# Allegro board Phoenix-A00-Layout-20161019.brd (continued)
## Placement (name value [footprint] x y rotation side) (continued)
RB11  0_5%  [R0402]  13.5 157.1 180 top
RB12  10K_5%  [R0402]  13.5 156.08 0 top
RB13  10K_5%  [R0402]  13.5 151 0 top
RB16  100_1%  [R0402]  10.7 118.36 180 top
RB17  0_5%  [R0402]  13.37 142.37 180 top
RB18  0_5%  [R0402]  15.4 142.37 0 top
RB19  0_5%  [R0402]  13.37 143.38 180 top
RB20  0_5%  [R0402]  15.4 143.38 0 top
RB21  0_5%  [R0402]  13.37 146.43 180 top
RB22  0_5%  [R0402]  15.4 146.43 0 top
RB23  0_5%  [R0402]  13.37 145.41 180 top
RB24  0_5%  [R0402]  15.4 145.41 0 top
RB25  0_5%  [R0402]  13.37 144.4 180 top
RB26  0_5%  [R0402]  15.4 144.4 0 top
RB27  0_5%  [R0402]  13.5 152.02 180 top
RB28  0_5%  [R0402]  15.4 147.45 0 top
RC1  1nF_X7R_16V  [C0402]  67.85 180.72 0 top
RD1  10K_5%  [R0402]  144.81 74.04 90 top
RD2  0_5%  [R0402]  149.77 75.18 90 top
RD3  470_1%  [R0402]  150.78 75.18 90 top
RD4  SHORT-PAD-4  [R0402_S4MIL_MVB]  151.8 75.18 270 top
RD5  240_1%  [R0402]  142.27 75.25 90 top
RD6  1K_1%  [R0402]  219.08 84.51 90 top
RD7  1K_1%  [R0402]  220.1 84.51 270 top
RD8  SHORT-PAD-10  [R0402_S10MIL_MVB]  221.09 84.53 270 top
RD9  2_1%  [R0402]  226.78 84.53 270 top
RD10  24.9_1%  [R0402]  228.91 84.53 270 top
REAR_AUDIO  HDA_X1_GF_Lime  [AUDIO_5_472X563_OBLONG]  233.67 256.72 0 top
RF1  3.3K_5%  [R0402]  198.79 223.52 0 top
RF2  15K_1%  [R0402]  201.71 221.87 270 top
RF3  6.2K_1%  [R0402]  203.23 222.38 0 top
RF4  0_5%  [R0805]  214.41 229.87 180 top
RF5  2.2K_5%  [R0402]  220.12 231.39 0 top
RF6  100_5%  [R0402]  237.78 136.52 0 top
RF7  0_5%  [R0402]  233.71 135.38 270 top
RF8  220_5%  [R0402]  236.51 118.62 90 top
RF9  1K_5%  [R0402]  235.49 118.62 270 top
RF10  0_5%  [R0805]  231.3 130.56 90 top
RF11  100K_1%  [R0402]  221.65 230.12 270 top
RF12  3K_1%  [R0402]  223.93 230.25 90 top
RF13  3.3K_5%  [R0402]  218.73 226.44 270 top
RF14  7.15K_1%  [R0603]  219.74 230.25 180 top
RF15  10K_1%  [R0402]  216.82 225.04 270 top
RF16  33_5%  [R0402]  27.08 109.09 180 top
RF17  33_5%  [R0402]  27.47 110.74 90 top
RF18  33_5%  [R0402]  27.47 112.78 270 top
RF21  33_5%  [R0402]  27.47 114.81 90 top
RF23  33_5%  [R0402]  28.48 103.38 270 top
RF24  33_5%  [R0402]  38.39 110.11 90 top
RF25  4.7K_5%  [R0402]  39.15 93.09 180 top
RF26  10K_5%  [R0402]  39.15 94.11 0 top
RF27  10K_5%  [R0402]  28.99 99.19 270 top
RF28  33_5%  [R0402]  30.01 94.62 0 top
RF29  10K_5%  [R0402]  33.56 89.92 90 top
RF30  10K_5%  [R0402]  39.15 95.12 0 top
RF32  0_5%  [R0402]  33.56 100.97 270 top
RF33  8.2K_5%  [R0402]  30.51 97.66 180 top
RF34  8.2K_5%  [R0402]  33.56 98.93 270 top
RF37  0_5%  [R0402]  30.01 95.63 0 top
RF39  0_5%  [R0402]  30.01 93.6 0 top
RF41  0_5%  [R0402]  32.29 89.92 90 top
RF43  0_5%  [R0402]  27.97 95.25 270 top
RF45  0_5%  [R0402]  30.01 96.65 0 top
RF53  0_5%  [R0402]  35.72 98.93 270 top
RF54  0_5%  [R0603]  38.39 97.79 270 top
RF55  0_5%  [R0603]  38.39 100.58 90 top
RF56  10K_5%  [R0402]  27.97 97.28 270 top
RF59  SHORT-PAD-15  [R0603_S15MIL_MVB]  39.15 105.41 0 top
RF60  33_5%  [R0402]  40.29 107.06 90 top
RF61  33_5%  [R0402]  38.77 107.44 180 top
RF62  0_5%  [R0603]  29.62 91.44 180 top
RF63  10K_5%  [R0402]  39.15 92.07 180 top
RF64  10K_5%  [R0402]  34.83 89.92 90 top
RF76  0_5%  [R0402]  27.47 125.98 0 top
RF77  2.2K_5%  [R0402]  20.99 149.73 0 top
RF176  30_5%  [R0402]  25.69 128.65 180 top
RF177  0_5%  [R0402]  25.31 125.98 0 top
RF178  22_5%  [R0402]  20.99 145.16 0 top
RF179  22_5%  [R0402]  23.02 149.73 0 top
RF180  0_5%  [R0805]  215.17 233.04 90 top
RG3  0_5%  [R0402]  149.53 220.22 270 top
RG4  0_5%  [R0402]  150.54 220.22 270 top
RG5  4.7K_5%  [R0402]  148.51 220.22 90 top
RG6  4.7K_5%  [R0402]  151.56 220.22 90 top
RG7  100K_5%  [R0402]  143.05 225.81 180 top
RG8  100K_5%  [R0402]  143.05 228.85 180 top
RG9  4.7K_5%  [R0402]  149.78 229.74 180 top
RG10  4.7K_5%  [R0402]  149.27 231.27 90 top
RG11  4.7K_5%  [R0402]  147.1 232.66 270 top
RG12  4.7K_5%  [R0402]  147.1 230.25 90 top
RG13  4.7K_5%  [R0402]  148.12 232.66 270 top
RG14  4.7K_5%  [R0402]  148.12 230.25 90 top
RG15  75_1%  [R0402]  155.99 224.28 90 top
RG16  75_1%  [R0402]  155.99 226.19 90 top
RG17  75_1%  [R0402]  155.99 228.09 90 top
RG18  36_1%  [R0402]  173.66 235.08 0 top
RG19  36_1%  [R0402]  171.12 235.08 0 top
RG20  2.2K_5%  [R0402]  156.75 232.66 0 top
RG21  2.2K_5%  [R0402]  156.75 231.65 0 top
RG22  10K_5%  [R0402]  190.84 232.54 90 top
RG23  0_5%  [R0402]  191.86 232.54 270 top
RG24  0_5%  [R0402]  161.72 233.17 90 top
RG25  0_5%  [R0402]  170.48 227.33 180 top
RG27  12K_1%  [R0402]  145.72 225.93 180 top
RG28  0_5%  [R0402]  144.18 215.77 0 top
RG29  100K_5%  [R0402]  142.65 218.57 90 top
RG30  0_5%  [R0402]  146.21 215.77 180 top
RG31  4.7K_5%  [R0402]  153.83 230.12 90 top
RG32  4.7K_5%  [R0402]  154.34 228.6 180 top
RH1  2.2K_5%  [R0402]  114.97 199.01 90 top
RH2  1K_5%  [R0402]  115.73 195.96 270 top
RH3  1K_5%  [R0402]  137.19 176.4 270 top
RH4  8.2K_5%  [R0402]  63.79 109.47 90 top
RH5  8.2K_5%  [R0402]  52.1 90.93 90 top
RH6  8.2K_5%  [R0402]  38.26 123.06 270 top
RH7  10K_5%  [R0402]  62.39 109.47 270 top
RH8  8.2K_5%  [R0402]  60.99 106.93 270 top
RH9  10K_5%  [R0402]  60.99 109.47 90 top
RH10  10K_5%  [R0402]  65.44 107.19 270 top
RI1  10_1%  [R0402]  217.84 242.19 180 top
RI2  10_1%  [R0402]  216.82 239.01 90 top
RI3  10_1%  [R0402]  225.2 239.01 90 top
RI4  10_1%  [R0402]  227.57 239.27 0 top
RIO2  1K_5%  [R0402]  213.84 20.62 270 top
RIO3  100_5%  [R0402]  214.86 20.62 270 top
RIO6  10K_5%  [R0402]  41.82 149.61 0 top
RIO8  499_1%  [R0603]  217.52 19.35 90 top
RIO9  390_1%  [R0603]  217.52 16.56 270 top
RIO10  1K_5%  [R0402]  201.96 12.4 180 top
RIO11  1K_5%  [R0402]  195.87 12.45 180 top
RK4  2.7K_5%  [R0402]  47.48 169.49 90 top
RK5  2.7K_5%  [R0402]  46.46 169.49 270 top
RK6  49.9_1%  [R0402]  57.56 186.44 90 top
RK7  232_1%  [R0603]  50.2 202.06 0 top
RK8  14.3K_1%  [R0402]  50.2 203.2 0 top
RK9  0_5%  [R0402]  51.34 207.77 270 top
RK10  0_5%  [R0402]  35.09 192.91 180 top
RK11  10K_5%  [R0402]  56.55 184.02 90 top
RK13  100_1%  [R0603]  34.58 206.63 0 top
RK14  0_5%  [R0402]  60.74 205.74 90 top
RK18  22_5%  [R0402]  63.03 186.44 270 top
RK19  0_5%  [R0402]  35.09 191.9 180 top
RK22  10K_5%  [R0402]  57.56 184.02 90 top
RK24  10K_5%  [R0402]  62.77 208.53 90 top
RK25  10K_5%  [R0402]  61.76 205.74 270 top
RK27  10K_5%  [R0402]  55.02 181.99 0 top
RK28  10K_5%  [R0402]  49.82 206.76 0 top
RK30  0_5%  [R0402]  26.58 219.71 0 top
RK31  10K_5%  [R0402]  53.88 187.58 90 top
RK32  10K_5%  [R0402]  61.76 208.53 90 top
RK33  10K_5%  [R0402]  58.58 186.44 90 top
RK34  1K_5%  [R0402]  55.41 205.74 270 top
RK35  1K_5%  [R0402]  52.87 205.28 0 top
RK36  10K_5%  [R0402]  55.41 208.34 90 top
RK37  10K_5%  [R0402]  63.03 184.02 270 top
RK38  10K_5%  [R0402]  56.55 186.44 270 top
RK39  10K_5%  [R0402]  54.39 205.74 270 top
RK40  0_5%  [R0402]  50.2 208.28 90 top
RK41  10K_5%  [R0402]  55.41 186.44 90 top
RK42  1K_5%  [R0402]  69.25 191.77 0 top
RK43  51K_1%  [R0402]  67.85 181.74 0 top
RK44  1K_1%  [R0402]  65.82 181.74 180 top
RK45  56K_1%  [R0402]  69.88 181.74 0 top
RK46  10K_5%  [R0402]  58.58 184.02 270 top
RK47  10K_5%  [R0402]  59.6 186.44 270 top
RK48  10K_5%  [R0402]  59.6 184.02 270 top
RK49  10K_5%  [R0402]  61.63 186.44 270 top
RK50  2.7K_5%  [R0402]  26.7 164.59 180 top
RK51  0_5%  [R0402]  26.82 193.32 0 top
RK52  0_5%  [R0402]  26.82 192.23 0 top
RK53  0_5%  [R0402]  26.61 218.77 0 top
RK54  2.7K_5%  [R0402]  26.7 165.61 0 top
RK55  100_1%  [R0603]  29.5 202.18 0 top
RK56  22_5%  [R0402]  60.61 186.44 270 top
RL1  10K_5%  [R0402]  102.4 226.57 0 top
RL3  4.7K_5%  [R0402]  106.97 221.23 90 top
RL12  0_5%  [R0402]  115.73 226.82 0 top
RL28  330_1%  [R0402]  115.73 223.77 0 top
RL29  330_1%  [R0402]  115.73 224.79 0 top
RL30  330_1%  [R0402]  115.73 225.81 0 top
RL32  SHORT-PAD-10  [R0402_S10MIL_MVB]  102.4 227.58 0 top
RL33  2.49K_1%  [R0402]  117.76 228.85 180 top
RL34  1K_5%  [R0402]  104.94 221.23 90 top
RL35  15K_5%  [R0402]  105.95 221.23 270 top
RL36  0_5%  [R0402]  115.48 221.36 270 top
RL37  10K_5%  [R0402]  54.14 250.19 0 top
RL38  SHORT-PAD-10  [R0402_S10MIL_MVB]  53.25 251.71 90 top
RL39  8.2K_5%  [R0402]  53.25 253.75 270 top
RL40  8.2K_5%  [R0402]  64.68 253.75 270 top
RL41  10K_5%  [R0402]  59.47 250.19 0 top
RL42  39K_5%  [R0402]  64.68 251.71 270 top
RL43  0_5%  [R0402]  66.96 253.75 90 top
RL44  0_5%  [R0402]  119.54 231.39 90 top
RM1  0_5%  [R0402]  100.74 144.53 90 top
RM2  1K_5%  [R0402]  99.73 144.53 90 top
RM3  10K_5%  [R0402]  102.78 144.91 180 top
RM4  0_5%  [R0402]  99.47 131.95 0 top
RM5  SHORT-PAD-4  [R0402_S4MIL]  101.51 133.22 270 top
RM6  10K_5%  [R0402]  112.43 132.21 180 top
RM7  10K_5%  [R0402]  110.14 132.46 0 top
RM8  1K_5%  [R0402]  113.19 133.73 270 top
RM15  0_5%  [R0402]  101.13 121.28 90 top
RM16  0_5%  [R0402]  100.11 121.28 90 top
RN5  4.7K_5%  [8P4R0603V]  153.96 238.46 0 top
RNF2  4.7K_5%  [8P4R0402V]  233.46 132.59 0 top
RNK1  8.2K_5%  [8P4R0603V]  58.33 206.25 0 top
RNK4  4.7K_5%  [8P4R0402V]  47.66 244.98 90 top
RNK5  8.2K_5%  [8P4R0603V]  69.07 194.18 270 top
RNK6  8.2K_5%  [8P4R0603V]  69.12 202.69 270 top
RNK7  4.7K_5%  [8P4R0402V]  26.96 241.17 90 top
RNO1  10K_5%  [8P4R0402V]  208.95 54.86 180 top
RNO2  8.2K_5%  [8P4R0603V]  205.11 16.41 270 top
RNO5  1K_5%  [8P4R0402V]  222.86 17.95 90 top
RNX4  4.7K_5%  [8P4R0402V]  87.41 232.03 0 top
RO2  SHORT-PAD-4  [R0402_S4MIL_MVB]  208.19 35.56 90 top
RO3  0_5%  [R0402]  213.77 55.5 180 top
RO4  SHORT-PAD-4  [R0402_S4MIL_MVB]  218.85 33.66 90 top
RO5  2M_5%  [R0402]  215.93 31.12 180 top
RO7  0_5%  [R0402]  213.77 54.48 180 top
RO8  SHORT-PAD-4  [R0402_S4MIL_MVB]  219.87 33.66 90 top
RO9  4.7K_5%  [R0402]  231.05 47.62 0 top
RO10  43_1%  [R0402]  223.3 31.24 90 top
RO11  160_5%  [R0402]  210.73 54.99 90 top
RO12  1K_5%  [R0402]  225.33 31.24 90 top
RO13  33_5%  [R0402]  212.5 34.54 270 top
RO16  SHORT-PAD-4  [R0402_S4MIL_MVB]  206.79 52.07 0 top
RO18  SHORT-PAD-4  [R0402_S4MIL_MVB]  206.79 53.09 0 top
RO19  SHORT-PAD-4  [R0402_S4MIL_MVB]  223.43 54.99 270 top
RO21  8.2K_5%  [R0402]  226.98 44.45 0 top
RO22  SHORT-PAD-4  [R0402_S4MIL_MVB]  222.41 54.99 90 top
RO23  10K_5%  [R0402]  211.23 56.51 180 top
RO24  0_5%  [R0402]  204.63 38.1 0 top
RO25  2.7K_5%  [R0402]  217.33 54.99 270 top
RO26  2.7K_5%  [R0402]  216.31 54.99 270 top
RO27  10K_5%  [R0402]  211.74 54.99 270 top
RO28  1K_5%  [R0402]  206.66 37.08 0 top
RO31  47K_5%  [R0402]  220.38 57.53 270 top
RO32  8.2K_5%  [R0402]  231.05 48.64 180 top
RO33  220_5%  [R0402]  226.98 48.9 180 top
RO35  15K_5%  [R0402]  220.38 54.99 270 top
RO36  330K_5%  [R0402]  226.73 33.66 270 top
RO39  8.2K_5%  [R0402]  206.15 35.56 90 top
RO43  30K_1%  [R0402]  204.5 50.04 180 top
RO44  9.1K_1%  [R0402]  200.19 47.88 90 top
RO45  7.15K_1%  [R0603]  199.04 48.26 270 top
RO46  10K_1%  [R0402]  7.15 69.6 0 top
RO48  33K_1%  [R0402]  200.31 50.55 270 top
RO50  20K_1%  [R0402]  7.15 70.61 0 top
RO51  9.1K_1%  [R0402]  204.5 51.05 180 top
RO52  10K_1%  [R0402]  12.86 69.72 90 top
RO53  1.65K_1%  [R0402]  7.4 72.14 90 top
RO54  6.8K_1%  [R0402]  204 52.58 90 top
RO55  30K_1%  [R0402]  214.92 61.09 180 top
RO56  8.2K_1%  [R0402]  213.39 61.59 270 top
RO57  698_1%  [R0402]  212.38 61.59 90 top
RO80  2.7K_5%  [R0402]  218.47 59.06 180 top
RO81  SHORT-PAD-4  [R0402_S4MIL_MVB]  221.39 54.99 270 top
RO89  33_5%  [R0402]  222.28 33.66 90 top
RO99  0_5%  [R0402]  215.3 54.99 270 top
RO100  10_1%  [R0402]  213.77 56.51 180 top
RO102  10_1%  [R0402]  217.33 61.09 180 top
RO117  8.2K_5%  [R0402]  231.05 49.66 180 top
RO118  10_1%  [R0402]  207.42 57.4 0 top
RO163  2.7K_5%  [R0402]  218.47 59.94 180 top
RO166  SHORT-PAD-4  [R0402_S4MIL_MVB]  229.4 45.47 180 top
RO167  22K_5%  [R0402]  221.39 57.53 90 top
RO168  30K_1%  [R0402]  204.63 44.83 90 top
RO169  8.2K_5%  [R0402]  207.17 35.56 270 top
RO170  2K_1%  [R0402]  200.31 52.58 270 top
RO171  9.1K_1%  [R0402]  200.06 44.07 90 top
RO172  10K_1%  [R0402]  201.58 43.56 180 top
RO174  0_5%  [R0402]  206.66 38.1 180 top
RO176  1K_5%  [R0402]  226.98 45.47 0 top
RO179  8.2K_5%  [R0402]  226.73 31.24 90 top
RO187  8.2K_5%  [R0402]  231.05 46.61 180 top
RO188  10_1%  [R0402]  221.9 28.96 270 top
RO189  16K_1%  [R0402]  14 69.72 270 top
RP5  51_5%  [R0402]  45.5 139.45 90 top
RP8  51_5%  [R0402]  48.17 144.02 90 top
RP25  10K_5%  [R0402]  54.26 109.22 270 top
RP26  SHORT-PAD-4  [R0402_S4MIL_MVB]  48.29 104.27 270 top
RP34  0_5%  [R0402]  62.14 139.95 0 top
RP35  0_5%  [R0402]  62.14 139.06 0 top
RP36  SHORT-PAD-15  [R0603_S15MIL_MVB]  58.33 109.6 270 top
RP37  SHORT-PAD-15  [R0603_S15MIL_MVB]  43.21 136.02 270 top
RP38  SHORT-PAD-15  [R0603_S15MIL_MVB]  46.13 109.35 90 top
RP40  10K_5%  [R0402]  54.26 106.81 90 top
RP41  10K_5%  [R0402]  60.99 102.11 90 top
RP42  SHORT-PAD-15  [R0603_S15MIL_MVB]  42.32 129.41 0 top
RS13  0_5%  [R0402]  56.93 90.81 90 top
RS14  0_5%  [R0402]  50.83 90.93 90 top
RS16  0_5%  [R0402]  116.75 195.96 270 top
RS17  0_5%  [R0402]  49.56 90.93 90 top
RS18  0_5%  [R0402]  43.57 102.59 0 top
RS21  0_5%  [R0402]  47.12 90.88 90 top
RS22  1K_5%  [R0402]  43.57 101.56 0 top
RS89  1K_5%  [R0402]  218.85 31.24 90 top
RS90  1K_5%  [R0402]  219.87 31.24 90 top
RS123  1K_1%  [R0402]  63.79 104.78 90 top
RS124  10K_5%  [R0402]  58.96 106.81 270 top
RS127  10K_5%  [R0402]  58.96 104.52 90 top
RS129  10K_5%  [R0402]  63.79 102.74 90 top
RS159  8.2K_5%  [R0402]  152.26 41.81 0 top
RS161  1K_5%  [R0402]  149.33 46.2 180 top
RS162  10K_5%  [R0402]  150.22 40.87 180 top
RS166  4.7K_5%  [R0402]  135.54 45.21 90 top
RS169  0_5%  [R0402]  116.24 197.43 180 top
RS222  1K_5%  [R0402]  150.22 41.81 180 top
RS223  0_5%  [R0402]  47.53 141.99 90 top
RS224  0_5%  [R0402]  45.25 141.99 90 top
RS225  0_5%  [R0402]  46.52 139.45 90 top
RS226  0_5%  [R0402]  47.53 139.45 90 top
RS227  1K_5%  [R0402]  46.52 141.99 270 top
RS232  1K_5%  [R0402]  45.05 101.79 270 top
RS233  10K_5%  [R0402]  46.13 106.43 270 top
RS234  1K_1%  [R0402]  46.13 104.14 270 top
RS235  10K_5%  [R0402]  40.55 114.05 0 top
RS236  1K_1%  [R0402]  42.83 114.05 0 top
RST_SWH  Tact Switch_Brown  [SW_2_236X150]  9.56 113.54 270 top
RTK_LAN  RTL8111HSD-CG_A  [QFN_32_16_157X157_TH106_H35]  110.65 227.2 270 top
RTK_VGA  RTD2168-CGT_E  [QFN32C1]  151.43 224.92 90 top
RU3  0_5%  [R0603]  97.52 245.87 180 top
RU4  0_5%  [R0603]  97.52 247.14 180 top
RU5  0_5%  [R0603]  97.52 243.33 180 top
RU10  0_5%  [R0603]  134.48 235.71 90 top
RU12  0_5%  [R0603]  133.21 235.71 90 top
RU13  0_5%  [R0603]  130.67 235.71 90 top
RU15  0_5%  [R0603]  131.94 235.71 90 top
RU26  10K_1%  [R0402]  131.22 228.98 180 top
RU29  15K_1%  [R0402]  130.72 227.46 270 top
RU46  8.2K_5%  [R0402]  63.79 107.19 270 top
RU47  15K_1%  [R0402]  137.32 21.42 270 top
RU54  0_5%  [R0603]  151.68 24.36 270 top
RU55  0_5%  [R0603]  150.41 24.36 270 top
RU58  0_5%  [R0603]  147.87 24.36 270 top
RU59  0_5%  [R0603]  149.14 24.36 270 top
RU62  0_5%  [R0603]  42.83 75.18 0 top
RU63  0_5%  [R0603]  42.83 73.91 0 top
RU66  0_5%  [R0603]  42.83 77.85 0 top
RU67  0_5%  [R0603]  42.83 76.58 0 top
RU68  15K_1%  [R0402]  55.41 75.18 180 top
RU69  10K_1%  [R0402]  55.66 73.66 270 top
RU120  0_5%  [R0603]  97.52 244.6 180 top
RU134  10K_1%  [R0402]  154.29 26.02 90 top
RU135  15K_1%  [R0402]  153.27 26.02 270 top
RU147  10K_1%  [R0402]  136.3 21.42 90 top
RU174  8.2K_5%  [R0402]  48.55 109.22 90 top
RV45  470_1%  [R0402]  208.57 244.98 90 top
RV46  470_1%  [R0402]  206.75 245.01 90 top
RV47  470_1%  [R0402]  205.48 245.01 90 top
RV48  470_1%  [R0402]  209.84 244.98 90 top
RV49  470_1%  [R0402]  211.58 245.01 270 top
RV72  470_1%  [R0402]  212.85 245.01 270 top
RV73  470_1%  [R0402]  214.63 245.01 270 top
RV74  470_1%  [R0402]  215.9 245.01 270 top
RV75  SHORT-PAD-4  [R0402_S4MIL_MVB]  219.49 235.97 90 top
RV76  SHORT-PAD-4  [R0402_S4MIL_MVB]  220.47 242.09 90 top
RV77  1M_5%  [R0402]  229.6 239.27 180 top
RV79  20K_5%  [R0402]  224.19 241.3 270 top
RV80  100K_5%  [R0402]  226.55 241.3 270 top
RV84  SHORT-PAD-4  [R0402_S4MIL_MVB]  222.54 235.97 90 top
RV85  SHORT-PAD-4  [R0402_S4MIL_MVB]  221.48 242.09 90 top
RV86  2.2K_1%  [R0402]  220.51 235.97 90 top
RV87  2.2K_1%  [R0402]  221.52 235.97 90 top
RV88  2.2K_1%  [R0402]  224.4 243.49 180 top
RV89  2.2K_1%  [R0402]  226.44 243.49 0 top
RX6  0_5%  [R0402]  86.52 227.46 90 top
RX7  0_5%  [R0402]  87.54 227.46 90 top
RX16  4.7K_5%  [R0402]  66.58 233.17 180 top
RX17  4.7K_5%  [R0402]  66.58 232.16 180 top
RX18  4.7K_5%  [R0402]  66.58 231.14 180 top
RX19  0_5%  [R0402]  66.58 235.2 180 top
RX20  0_5%  [R0402]  66.58 234.19 180 top
RX21  150_1%  [R0402]  126.15 193.04 0 top
RX165  10K_5%  [R0402]  64.8 215.52 180 top
RX175  0_5%  [R0402]  75.6 234.7 0 top
RX176  0_5%  [R0402]  75.6 233.68 0 top
RX181  33_5%  [R0402]  49.56 250.7 180 top
RX182  SHORT-PAD-4  [R0402_S4MIL_MVB]  46.39 251.71 180 top
RX185  10K_1%  [R0402]  33.05 119.25 0 top
RX199  SHORT-PAD-4  [R0402_S4MIL_MVB]  41.31 142.11 90 top
RX200  33_5%  [R0402]  42.32 144.65 90 top
RX201  0_5%  [R0402]  42.32 142.11 90 top
RX202  0_5%  [R0402]  41.31 144.65 90 top
SATA0  SATA_S_15u_Blue  [SATA7_LE18]  121.67 70.41 0 top
SATA1  SATA_S_15u_White  [SATA7_LE18]  139.9 70.41 0 top
SATA2  SATA_S_15u_Black  [SATA7_LE18]  139.9 59.81 0 top
SATA_PWR  PWR_2X3_K6_4.2_Black  [PWR_2X3_165_547X378_O6]  104.36 41.07 180 top
SIO_5553  SCH5553-NU_C  [VTQFP_128_16_630]  216.69 44.69 90 top
SLOT1  PCIE-X16_164P_15u_Blue  [PCIE164_X16_RM_POUDRE]  83.15 238.78 90 top
SLOT2  PCIEX1_36P_15u_Black  [PCIE36_X1]  61.43 227.13 270 top
SLOT3  PCI_120P_15u  [PCI120]  41.11 244.85 0 top
SLOT4  PCI_120P_15u  [PCI120]  20.79 244.85 0 top
SPI1  MX25L12873FM2I-10G  [SOP8JG]  32.93 108.84 90 top
SPI_1  SPI_8P_100u_Black  [SOP8JA_SOCKET2]  32.93 108.84 270 top
SSUSB_R  USB3X2_15u_Blue  [USB3X4_18_79]  134.41 247.1 180 top
SW_FVS  TEST POINT  [FVS_DELL]  211.87 24.72 0 top
THRM_1  ST2N3904-TDF4001-HAF  [TO92_EBC_H310]  7.59 79.63 270 top
THRM_2  ST2N3904-TDF4001-HAF  [TO92_EBC_H310]  68.11 148.97 270 top
TPS1  TP_SMD  [TPC30B]  43.21 121.54 0 top
TPS5  TP_SMD  [TPC30B]  211.49 47.37 0 top
TPS8  TP_SMD  [TPC30B]  170.47 141.1 0 top
TPS9  TP_SMD  [TPC30B]  169.61 139.34 0 top
TPS13  TP_SMD  [TPC22B30D12]  146.97 129.34 0 top
TPS14  TP_SMD  [TPC22B30D12]  146.31 130.91 0 top
TPS19  TP_SMD  [TPC30B]  156.45 157.15 0 top
TPS20  TP_SMD  [TPC30B]  155.86 164.8 0 top
TPS21  TP_SMD  [TPC22B30D12]  184.11 129.97 0 top
TPS22  TP_SMD  [TPC22B30D12]  182.84 128.9 0 top
TPS24  TP_SMD  [TPC30B]  183.73 165.53 0 top
TPS25  TP_SMD  [TPC30B]  153.96 140.08 0 top
TPS26  TP_SMD  [TPC22B30D12]  185.15 130.89 0 top
TPS27  TP_SMD  [TPC22B30D12]  184.72 128.63 0 top
TPS28  TP_SMD  [TPC30B]  155.71 139.29 0 top
TPS29  TP_SMD  [TPC30B]  183.17 145.44 0 top
TPS30  TP_SMD  [TPC30B]  154.44 154.86 0 top
TPS41  TP_SMD  [TPC30B]  156.5 162.81 0 top
TPS42  TP_SMD  [TPC30B]  158.3 160.3 0 top
TPS43  TP_SMD  [TPC30B]  158.12 158.37 0 top
TPS44  TP_SMD  [TPC30B]  185.3 147.09 0 top
TPS45  TP_SMD  [TPC30B]  157.94 164.69 0 top
TPS46  TP_SMD  [TPC30B]  186.16 145.19 0 top
TPS70  TP_SMD  [TPC30B]  52.56 127.35 0 top
TPS71  TP_SMD  [TPC30B]  53.63 125.6 0 top
TPS72  TP_SMD  [TPC30B]  172.22 139.06 0 top
TPS73  TP_SMD  [TPC30B]  47.61 136.93 0 top
TPS74  TP_SMD  [TPC30B]  47.02 135.03 0 top
TPS75  TP_SMD  [TPC30B]  52.23 123.83 0 top
TPS76  TP_SMD  [TPC30B]  52.46 121.39 0 top
TPS77  TP_SMD  [TPC30B]  54.34 131.04 0 top
TPS78  TP_SMD  [TPC30B]  56.06 129.94 0 top
TPS79  TP_SMD  [TPC22B30D12]  54.97 128.22 0 top
TPS80  TP_SMD  [TPC22B30D12]  57.26 128.19 0 top
TPS81  TP_SMD  [TPC22B30D12]  58.52 130.01 0 top
TPS82  TP_SMD  [TPC30B]  59.44 128.32 0 top
TPS83  TP_SMD  [TPC30B]  61.73 129.18 0 top
TPS84  TP_SMD  [TPC30B]  60.49 121.06 0 top
TPS85  TP_SMD  [TPC30B]  60.89 124.79 0 top
TPS86  TP_SMD  [TPC30B]  59.24 119.05 0 top
TPS87  TP_SMD  [TPC30B]  61.48 119.05 0 top
TPS88  TP_SMD  [TPC30B]  62.01 122.76 0 top
TPS89  TP_SMD  [TPC30B]  62.82 124.49 0 top
TPS90  TP_SMD  [TPC30B]  63 117.88 0 top
TPS91  TP_SMD  [TPC30B]  63.25 119.79 0 top
TPS94  TP_SMD  [TPC22B30D12]  154.54 157.48 0 top
TPS95  TP_SMD  [TPC22B30D12]  160.03 158.39 0 top
TPS96  TP_SMD  [TPC30B]  158.58 156.46 0 top
TPS99  TP_SMD  [TPC30B]  160.05 164.72 0 top
TPS101  TP_SMD  [TPC30B]  185.07 163.83 0 top
TPS102  TP_SMD  [TPC30B]  158.3 154.51 0 top
TPS103  TP_SMD  [TPC22B30D12]  156.4 154.53 0 top
TPS105  TP_SMD  [TPC22B30D12]  152.71 158.39 0 top
TPS106  TP_SMD  [TPC30B]  54.77 201.55 0 top
TPS107  TP_SMD  [TPC30B]  56.68 203.33 0 top
TPS108  TP_SMD  [TPC30B]  56.8 201.29 0 top
TPS109  TP_SMD  [TPC22B30D12]  182.34 160.21 0 top
TPS110  TP_SMD  [TPC30B]  180.41 160.05 0 top
TPS120  TP_SMD  [TPC30B]  64.17 129.41 0 top
TPS121  TP_SMD  [TPC30B]  63.15 127.46 0 top
TPS122  TP_SMD  [TPC30B]  70.77 127.76 0 top
TPS123  TP_SMD  [TPC30B]  68.87 125.86 0 top
TPS124  TP_SMD  [TPC30B]  66.07 129.41 0 top
TPS125  TP_SMD  [TPC30B]  67.98 129.54 0 top
TPS126  TP_SMD  [TPC30B]  68.87 127.76 0 top
TPS127  TP_SMD  [TPC30B]  66.96 125.86 0 top
TPS128  probe  [TPC30B]  53.37 113.92 0 top
TPS129  probe  [TPC30B]  53.37 111.76 0 top
TPS130  probe  [TPC30B]  52.74 116.08 0 top
TPS131  probe  [TPC30B]  52.99 117.98 0 top
TPS132  probe  [TPC30B]  49.09 116.91 0 top
TPS133  probe  [TPC30B]  47.2 117.35 0 top
U1  SN74LVC1G00DCKR  [SC70_5]  45.5 253.49 0 top
U4  GLH110_D1,SR2CA  [BGA_837_906X906]  57.31 124.46 0 top
U122  MMDT3904-7-F  [SOT363V]  236 120.9 180 top
U136  MAX9892ERT+  [UCSP_6_20_60X39]  232.82 239.58 270 top
U139  SN74AUP1G08DCKR  [SC70_5]  146.71 74.65 90 top
U*  -  [#2]  158.02 107.57 180 bottom
UA1  ALC3234-CGT_A2  [QFN_48_16_236X236_TH173]  185.58 23.83 270 top
UA2  APL5325BI-TRG  [SOT23_5]  200.06 21.92 270 top
UEFI  TEST POINT  [FVS_DELL]  70.01 101.85 270 top
UF1  NPCT650JB1YX_E  [QFN32C1_H31]  34.58 94.36 180 top
UF2  Z32H320TC-LPC-Q32-412  [TQFN_32_20_197_TH124]  22 156.21 270 top
UF3  CDCLVC1102PWR  [TSSOP8FA]  22.13 147.45 0 top
UF147  LM358DR2G  [SOP8JA]  222.03 225.17 180 top
UK2  APL5325BI-TRG  [SOT23_5]  69.38 184.53 270 top
UL5  CMC_90_330mA  [L4S12X20V_H43]  165.09 23.3 90 top
UL19  CMC_90_330mA  [L4S12X20V_H43]  162.55 23.3 90 top
UO2  GD75232DBRE4  [SSOP20FB]  184.06 229.76 270 top
UR13  0_5%  [R0603]  165.72 23.3 270 top
UR14  0_5%  [R0603]  164.45 23.3 270 top
UR57  0_5%  [R0603]  161.91 23.3 270 top
UR58  0_5%  [R0603]  163.18 23.3 270 top
US1_1  HEATSINK_PCH  [HS_2C_906X906]  57.31 124.46 90 top
UU1  AZC199-04S.R7G_16KV  [SOT23_6]  101.08 245.24 270 top
UU3  AZC199-04S.R7G_16KV  [SOT23_6]  132.95 239.39 0 top
UU4  AZC199-04S.R7G_16KV  [SOT23_6]  163.82 19.87 180 top
UU6  AOZ8809DI-05_15KV  [DFN_10_20_39]  137.78 238.89 0 top
UU7  AOZ8809DI-05_15KV  [DFN_10_20_39]  128.51 238.89 0 top
UU9  AZC199-04S.R7G_16KV  [SOT23_6]  149.78 20.81 0 top
UU10  AOZ8809DI-05_15KV  [DFN_10_20_39]  141.02 19.67 180 top
UU13  AZC199-04S.R7G_16KV  [SOT23_6]  46.39 75.82 90 top
UU17  SRV05-4HTG  [SOT23_6]  100.87 230 0 top
UU18  SRV05-4HTG  [SOT23_6]  123.94 236.6 90 top
UU26  AOZ8809DI-05_15KV  [DFN_10_20_39]  145.72 19.67 180 top
UU27  AZC199-04S.R7G_16KV  [SOT23_6]  148.75 236.22 270 top
UV7  AOZ8809DI-05_15KV  [DFN_10_20_39]  221.73 244.35 0 top
UX1  SN74LVC1G14DBVRE4  [SOT23_5]  49.56 252.98 0 top
VGA_COM  VGA_Blue+RS232_Teal_15u  [DSUBX2_24_1220X887]  189.68 239.13 180 top
WF_BT_USB  Header_2X7_K9_GF_Black  [H2X7MZO9]  52.24 72.81 180 top
XDP_CPU  ITP_2X30_GF  [HMS2X30CZ_MVB_DELL]  126.41 201.8 0 top
XDP_PCH  ITP_2X30_GF  [HMS2X30CZ_MVB_DELL]  51.19 96.49 180 top
XL1  25MHz  [X2O]  124.24 227.71 270 top
Y1  24MHz  [X4S32X25]  77.25 132.21 270 top
Y5  32.768KHz  [X4S38X80]  34.45 134.24 0 top

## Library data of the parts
APS/PETS = HEADER_2X7_FLASH
ATX_CPU = ATX_2X2_2
ATX_SYS = ATX_2X4_1
AUX_PWR1 = LED6
BATTERY = BAT_SOCKET-2
BH1 PU21 = 74AUP1G17_5PIN
BRIDGE = XIO2001ZGU_169PIN
C1-C3 C5 C20-C25 C48-C51 C57-C75 C228 C379 C383 C386 C409-C415 C531 C558 C766 C1629 C1630 C1639-C1649 C1654-C1657 C1660 C1661 C1664-C1668 C1670-C1672 C1677-C1679 C1681-C1684 C1686 C1688 C1689 C1722-C1724 C1728 C1763 C1764 C1766-C1769 C1807 C1808 CA1-CA12 CA15-CA25 CA27-CA29 CA74-CA80 CA82-CA92 CA101-CA111 CA116-CA126 CB1-CB5 CD1-CD6 CF1 CF2 CF4-CF14 CF18-CF24 CF103-CF109 CG7-CG27 CK1-CK16 CK19 CK20 CK23 CK25-CK54 CK56 CK58-CK68 CL5 CL6 CL15 CL17 CL23 CL31-CL36 CL41-CL59 CM5 CM6 CO1-CO14 CO16-CO20 CO32 CO33 CO42 CO51-CO56 CS69 CS73 CS75 CS78 CS82-CS84 CS97 CS111 CS112 CS118 CS120 CS126 CS128 CS129 CS131-CS133 CS140-CS145 CS148 CS154 CS156 CS161 CS162 CS165 CS166 CS171 CS175-CS218 CU2 CU3 CU5 CU10 CU11 CU13 CU14 CU79 CV40-CV42 CX1 CX14 CX18-CX20 CX25 CX54-CX57 CX83 CX84 PC1 PC2 PC17 PC18 PC21 PC22 PC24-PC26 PC30 PC32-PC50 PC57-PC59 PC61-PC73 PC79-PC111 PC114-PC117 PC119 PC121-PC125 PC128-PC144 PC148-PC155 PC158-PC162 PC166-PC175 PC178 PC180-PC193 PC195-PC204 PC206-PC211 PC229-PC231 PC234 PC236 PC240 PC241 PC258 PC261 PC262 PC293-PC298 PC300-PC305 PC308-PC313 PC315 PC316 PC319-PC350 RC1 = CAP
C6-C9 C19 C52-C56 = CAP: room: CRT
CF3 CF110 ECK1 ECK3-ECK7 ECU2 ECU3 ECU6 ECU7 ECU9 ECU10 ECU13 ECX7 ECX10-ECX12 PC179 PCE1-PCE4 PCE7 PCE8 PCE12-PCE19 PCE21-PCE28 PCE30-PCE37 = ECAP
CG1-CG6 CL1-CL4 CM1-CM4 CO25-CO28 CO43-CO46 CSA1-CSA12 CV32-CV39 CX15-CX17 CX21-CX24 CX26-CX39 CX41-CX47 CX52 CX53 CX98-CX101 CX118 CX119 CX126 CX127 = CAP: signal model: CAP_C0402
CNO1 CNO2 = CAPA
COOLER = MTG-HOLE-8_4
CPO1 CPO2 R73 R6375 R6378 R6380 R6383 R6388 R6523 R6575 R6577 R6578 R6660-R6663 RA19 RD4 RM5 RO2 RO4 RO8 RO16 RO18 RO19 RO22 RO81 RO166 RP26 RV75 RV76 RV84 RV85 RX182 RX199 = Short Pad-4
CPU = PE115127-4041-0DH
CPU_2 = CPU_ILM_3PIN
D1 D5 = BAT54C
D41 = BAT54A-7
DA4-DA6 = AZ5125-02S_3PIN
DA7 = DIODE_ESD_DUAL_0
DF1 DG4 DO2 DO3 = DIODE_NORMAL
DG1-DG3 DG5-DG8 = BAV99
DIMM1 DIMM2 = DDR4_288PIN
DO1 = DIODE_SCHOTTKY
EEPROM_G = M24256-BWMN6TP_8P
F2 F6 FG1 = FUSE
F_AUDIO = AUDIO_6PIN_1
F_USB2 = USBX2
F_USB3 SSUSB_R = USB3X2_18PIN
FAN_CPU = Header_1X4
FAN_SYS = HEADER_1X3_FAN3P
FBA1-FBA5 FBG1 FBG2 FBK1 FBK3 IO_FBI7-IO_FBI14 L13-L16 PFB2-PFB4 PFB10-PFB12 = FB
FM1-FM5 FM7 = MTG157-RD276-N-4C8_13
FU2 FU5 FU6 FU9 = FUSE_2
FVS SW_FVS UEFI = FVS_0
HDD_LED = LED_SOCKET_2PIN
HDMI = HDMI_19PIN_3
HS_CLIP1 HS_CLIP2 = CLIP_2PIN_1
INT_SPKR = HEADER_1X4
KYBD_MOUSE = PS2-KBMS-2
L60-L62 = CL
LG1-LG3 PL11 = INDUCTOR_CHILISIN
LL2 PL2-PL10 PL12 PL13 PL15 = COIL
LPC_DEBUG = Header_2x7_K10
LU1 LU2 LU4 LU23 LU24 LU35-LU37 UL5 UL19 = COMMON CHOKE_1
M.2_SSD = NGFF_67PIN
MH1-MH8 = MTG-HOLE-8_19
MH21 MH22 = MTG-HOLE-8_22
NIC_USB = USBX2+RJ45_15U_BLACK_1
P1-P3 PAD1 = HEADER_1X2
PD2 PD8 = BAR90-02LRH_2PIN
PD3 PD5 PD6 = DIODE_ZENER
PJP2 PJP4 PR65 PR148 PR149 PR153 PR161 PR208 PR223 PR276 PR320 R62 RD8 RL32 RL38 = short pad-10
PJP9-PJP20 PJP30-PJP32 = Short pad for sense
PPID = PPID
PQ2 PQ13 = MOSFET_P_6PIN_1
PQ3 PQ4 PQ19 PQ22 PQ24 PQ49 PQ52 PQ55 PQ78 QS11 = 2N7002DWA_7_6PIN
PQ7 PQ11 QL7 = MOSFET_P
PQ9 PQ16 PQ21 PQ46 PQ57 PQ71 Q3 QF1 QV72 = MOSFET_N_1
PQ15 PQ17 PQ29-PQ43 PQ48 PQ58-PQ61 = MOS N_SO8FL
PQ20 PQ72 PQ79 QM2 QO1-QO6 QO12 QO14 U122 = NPN_DUAL
PQ23 PQ50 PQ51 PQ54 QA3 QA4 QG1 = MOSFET_N
PQ44 = BSC0925ND_7PIN
PQ45 = FDMS3604S_9PIN
PQ47 PQ76 QL4-QL6 QM1 THRM_1 THRM_2 = NPN
PQ53 = AON7401L_3PIN
PR8 PR11 PR12 PR14 PR15 PR17 PR22 PR24-PR28 PR30-PR32 PR34-PR36 PR39-PR57 PR61 PR67-PR71 PR73-PR78 PR87-PR147 PR150-PR152 PR154-PR160 PR162-PR207 PR209-PR217 PR219-PR222 PR224 PR230-PR246 PR248-PR250 PR252 PR254 PR256-PR275 PR279 PR282-PR284 PR317 PR336 PR337 PR344 PR345 PR347 PR348 PR353 PR358 PR361 PR380-PR389 PR391 PR392 R1-R3 R7-R9 R12 R15-R17 R19-R22 R25-R27 R30 R31 R33 R37-R40 R45-R52 R60 R61 R63 R65 R67-R69 R71 R72 R74 R77 R79-R81 R83 R86-R90 R92 R93 R96-R98 R101-R103 R106 R108 R109 R112 R114 R116-R119 R121 R148 R149 R152 R381 R495 R497 R508 R663 R6255 R6289 R6290 R6296 R6298 R6331 R6339 R6341 R6346-R6348 R6350-R6352 R6369 R6391-R6394 R6403 R6408 R6413 R6418 R6423 R6425 R6427 R6431 R6434 R6435 R6438 R6442 R6453 R6464-R6469 R6471-R6473 R6500 R6513 R6533 R6538-R6541 R6544 R6546 R6573 R6574 R6576 R6579-R6582 R6585 R6586 R6590 R6591 R6595 R6596 R6602 R6603 R6605 R6613-R6615 R6618 R6619 R6628 R6636 R6642 R6643 R6649 R6655 R6658 R6659 R6664 R6665 R6668 R6669 R6680-R6682 RA1 RA2 RA4-RA18 RA20-RA22 RA33-RA37 RA40-RA44 RA58 RA59 RA69-RA77 RB1-RB13 RB16-RB28 RD1-RD3 RD5-RD7 RD9 RD10 RF1-RF18 RF21 RF23-RF30 RF32-RF34 RF37 RF39 RF41 RF43 RF45 RF53-RF56 RF60-RF64 RF76 RF77 RF176-RF180 RG3-RG25 RG27-RG32 RH1-RH10 RI1-RI4 RIO2 RIO3 RIO6 RIO8-RIO11 RK4-RK11 RK13 RK14 RK18 RK19 RK22 RK24 RK25 RK27 RK28 RK30-RK56 RL1 RL3 RL12 RL28-RL30 RL33-RL37 RL39-RL44 RM1-RM4 RM6-RM8 RO3 RO5 RO7 RO9-RO13 RO21 RO23-RO28 RO31-RO33 RO35 RO36 RO39 RO43-RO46 RO48 RO50-RO57 RO80 RO89 RO99 RO100 RO102 RO117 RO118 RO163 RO167-RO172 RO174 RO176 RO179 RO187-RO189 RP5 RP8 RP25 RP34 RP35 RP40 RP41 RS13 RS14 RS16-RS18 RS21 RS22 RS89 RS90 RS123 RS124 RS127 RS129 RS159 RS161 RS162 RS166 RS169 RS222-RS227 RS232-RS236 RU26 RU29 RU46 RU47 RU68 RU69 RU134 RU135 RU147 RU174 RV45-RV49 RV72-RV74 RV77 RV79 RV80 RV86-RV89 RX6 RX7 RX16-RX21 RX165 RX175 RX176 RX181 RX185 RX200-RX202 = RES
PRT1-PRT4 = RT
PU2 PU13 = RT8237EZQW_11PIN
PU3 = RT9045ZSP_9PIN
PU5 = AOZ2262QI-18_23PIN
PU6 = AZ34063UMTR-G1_8pin
PU7 = RT3607CEGQW_57PIN
PU8-PU12 = RT9624BZQWA_9Pin
PU14 = APL5611CI-TRG_6PIN
PU16 = RT6576DGQW_21PIN
PU18 = RT7296FGJ8F_8PIN
PU20 = RT9742CGJ5F_5PIN
PWR_SW = SWITCH_4PIN_2
Q99 Q104 QV22 QV49 = FDV301N
QF2 QS10 = PNP
R70 R75 R78 R82 R85 R91 R99 R100 R104 R105 R6518 R6531 R6604 R6606-R6608 = RES: room: ADPT_IN
R6566 R6568 R6638-R6641 RF59 RP36-RP38 RP42 = SHORT PAD-15
REAR_AUDIO = JACK-AUD_5PIN_3
RM15 RM16 = RES: signal model: RES_R0402
RN5 RNF2 RNK1 RNK4-RNK7 RNO1 RNO2 RNO5 RNX4 = RESA_8P4R
RST_SWH = SMD_SWITCH_2
RTK_LAN = RTL8111HSD_CG_33PIN
RTK_VGA = RTD2168-CG_33PIN
RU3-RU5 RU10 RU12 RU13 RU15 RU54 RU55 RU58 RU59 RU62 RU63 RU66 RU67 RU120 UR13 UR14 UR57 UR58 = RES: signal model: RES_R0603
SATA0-SATA2 = SATA
SATA_PWR = ATX_PWR_5P
SIO_5553 = SCH5553-NU_128PIN
SLOT1 = PCIEX16_164P_15U
SLOT2 = PCI EXPRESS X1_SLOT
SLOT3 SLOT4 = PCI_SLOT_120P_3
SPI1 = MX25L12873FM2I-10G_8Pin
SPI_1 = SOCKET_8PIN
TPS1 TPS5 TPS8 TPS9 TPS13 TPS14 TPS19-TPS22 TPS24-TPS30 TPS41-TPS46 TPS70-TPS91 TPS94-TPS96 TPS99 TPS101-TPS103 TPS105-TPS110 TPS120-TPS127 = TEST POINT
TPS128-TPS133 = TEST_POINT_0
U1 = SN74LVC1G32DRLR_0
U4 = SUNRISE POINT_H110_837PIN
U136 = MAX9892ERT+_6PIN
U139 = AND_GATE
UA1 = ALC3234-CG_48PIN
UA2 UK2 = APL5325BI-TRG_5PIN
UF1 = NPCT650JB2YX_32PIN
UF2 = Z32H320TC-LPC-Q32-412_32PIN
UF3 = CDCLVC1102PWR_8P
UF147 = LM158_258_358_2904
UO2 = SN75185
US1_1 = Heatsink_2
UU1 UU3 UU4 UU9 UU13 UU27 = AZC199-04S_6PIN
UU6 UU7 UU10 UU26 UV7 = AOZ8809_9PIN
UU17 UU18 = TVS_6Pin
UX1 = SN74LVC1G14
VGA_COM = COM_PORT
WF_BT_USB = HEADER_2X7_K9_15U_YELLOW
XDP_CPU = BSH-030-01-F-D-A-TR_0
XDP_PCH = BSH-030-01-F-D-A-TR
XL1 = XTAL-2P
Y1 = XTAL_25.000M_SMD-4P
Y5 = XTAL-SMD-4P

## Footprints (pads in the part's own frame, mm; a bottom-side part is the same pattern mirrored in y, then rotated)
8P4C0603
  oval 0.508x1.016 smd: 1(-1.2,-0.762) 2(-1.2,0.762) 3(-0.4,-0.762) 4(-0.4,0.762) 5(0.4,-0.762) 6(0.4,0.762) 7(1.2,-0.762) 8(1.2,0.762)
8P4R0402V
  oval 0.279x0.762 smd: 1(-0.762,-0.508) 2(-0.254,-0.508) 3(0.254,-0.508) 4(0.762,-0.508) 5(0.762,0.508) 6(0.254,0.508) 7(-0.254,0.508) 8(-0.762,0.508)
8P4R0603V
  oval 0.508x1.016 smd: 1(-1.2,-0.762) 2(-0.4,-0.762) 3(0.4,-0.762) 4(1.2,-0.762) 5(1.2,0.762) 6(0.4,0.762) 7(-0.4,0.762) 8(-1.2,0.762)
0603
  oval 0.914x0.813 smd: 1(-0.686,0) 2(0.686,0)
0603_H37
  oval 0.914x0.813 smd: 1(-0.686,0) 2(0.686,0)
0805
  oval 1.016x1.27 smd: 1(-0.889,0) 2(0.889,0)
1212H59
  oval 1.143x3.302 smd: 1(-1.079,0) 2(1.079,0)
2424H45
  rect 1.626x5.74 smd: 1(-2.35,0) 2(2.35,0)
AUDIO_5_472X563_OBLONG
  oval 1.702x2.261 hole 0.94x1.499: 1(0,0)
  oval 1.422x2.159 hole 0.66x1.397: 2(-5,-5) 3(-2.5,-5) 4(2.5,-5) 5(5,-5)
AUDIO_6_374X463
  round 1.219 hole 1.219 unplated: (3.8,9.1) (3.8,3.1)
  oval 1.118x1.905 hole 0.61x1.397: 1(0,0) 2(7.5,7.1) 3(0.1,9.05) 4(6.5,9.05) 5(6,0) 6(7.6,0) 7(-0.8,5.6) 8(8.4,4.6)
BAT2_200D223-1
  round 1.829 hole 1.321: 1(11.85,0) 2(-8.15,0)
BGA_169_472X472
  round 0.406 smd: A1(-4.8,4.8) A2(-4,4.8) A3(-3.2,4.8) A4(-2.4,4.8) A5(-1.6,4.8) A6(-0.8,4.8) A7(0,4.8) A8(0.8,4.8) A9(1.6,4.8) A10(2.4,4.8) A11(3.2,4.8) A12(4,4.8) A13(4.8,4.8) B1(-4.8,4) B2(-4,4) B3(-3.2,4) B4(-2.4,4) B5(-1.6,4) B6(-0.8,4) B7(0,4) B8(0.8,4) B9(1.6,4) B10(2.4,4) B11(3.2,4) B12(4,4) B13(4.8,4) C1(-4.8,3.2) C2(-4,3.2) C3(-3.2,3.2) C4(-2.4,3.2) C5(-1.6,3.2) C6(-0.8,3.2) C7(0,3.2) C8(0.8,3.2) C9(1.6,3.2) C10(2.4,3.2) C11(3.2,3.2) C12(4,3.2) C13(4.8,3.2) D1(-4.8,2.4) D2(-4,2.4) D3(-3.2,2.4) D4(-2.4,2.4) D5(-1.6,2.4) D6(-0.8,2.4) D7(0,2.4) D8(0.8,2.4) D9(1.6,2.4) D10(2.4,2.4) D11(3.2,2.4) D12(4,2.4) D13(4.8,2.4) E1(-4.8,1.6) E2(-4,1.6) E3(-3.2,1.6) E4(-2.4,1.6) E5(-1.6,1.6) E6(-0.8,1.6) E7(0,1.6) E8(0.8,1.6) E9(1.6,1.6) E10(2.4,1.6) E11(3.2,1.6) E12(4,1.6) E13(4.8,1.6) F1(-4.8,0.8) F2(-4,0.8) F3(-3.2,0.8) F4(-2.4,0.8) F5(-1.6,0.8) F6(-0.8,0.8) F7(0,0.8) F8(0.8,0.8) F9(1.6,0.8) F10(2.4,0.8) F11(3.2,0.8) F12(4,0.8) F13(4.8,0.8) G1(-4.8,0) G2(-4,0) G3(-3.2,0) G4(-2.4,0) G5(-1.6,0) G6(-0.8,0) G7(0,0) G8(0.8,0) G9(1.6,0) G10(2.4,0) G11(3.2,0) G12(4,0) G13(4.8,0) H1(-4.8,-0.8) H2(-4,-0.8) H3(-3.2,-0.8) H4(-2.4,-0.8) H5(-1.6,-0.8) H6(-0.8,-0.8) H7(0,-0.8) H8(0.8,-0.8) H9(1.6,-0.8) H10(2.4,-0.8) H11(3.2,-0.8) H12(4,-0.8) H13(4.8,-0.8) J1(-4.8,-1.6) J2(-4,-1.6) J3(-3.2,-1.6) J4(-2.4,-1.6) J5(-1.6,-1.6) J6(-0.8,-1.6) J7(0,-1.6) J8(0.8,-1.6) J9(1.6,-1.6) J10(2.4,-1.6) J11(3.2,-1.6) J12(4,-1.6) J13(4.8,-1.6) K1(-4.8,-2.4) K2(-4,-2.4) K3(-3.2,-2.4) K4(-2.4,-2.4) K5(-1.6,-2.4) K6(-0.8,-2.4) K7(0,-2.4) K8(0.8,-2.4) K9(1.6,-2.4) K10(2.4,-2.4) K11(3.2,-2.4) K12(4,-2.4) K13(4.8,-2.4) L1(-4.8,-3.2) L2(-4,-3.2) L3(-3.2,-3.2) L4(-2.4,-3.2) L5(-1.6,-3.2) L6(-0.8,-3.2) L7(0,-3.2) L8(0.8,-3.2) L9(1.6,-3.2) L10(2.4,-3.2) L11(3.2,-3.2) L12(4,-3.2) L13(4.8,-3.2) M1(-4.8,-4) M2(-4,-4) M3(-3.2,-4) M4(-2.4,-4) M5(-1.6,-4) M6(-0.8,-4) M7(0,-4) M8(0.8,-4) M9(1.6,-4) M10(2.4,-4) M11(3.2,-4) M12(4,-4) M13(4.8,-4) N1(-4.8,-4.8) N2(-4,-4.8) N3(-3.2,-4.8) N4(-2.4,-4.8) N5(-1.6,-4.8) N6(-0.8,-4.8) N7(0,-4.8) N8(0.8,-4.8) N9(1.6,-4.8) N10(2.4,-4.8) N11(3.2,-4.8) N12(4,-4.8) N13(4.8,-4.8)
BGA_837_906X906
  round 0.305 smd: A2(10.814,10.46) A3(10.814,9.959) A4(10.814,9.459) A42(10.814,-9.459) A43(10.814,-9.959) A44(10.814,-10.46) AA17(0.775,3.099) AA18(0.775,2.324) AA20(0.775,1.549) AA21(0.775,0.775) AA23(0.775,0) AA25(0.775,-0.775) AA26(0.775,-1.549) AA28(0.775,-2.324) AA29(0.775,-3.099) AB7(0.667,8.175) AB8(0.667,7.413) AB10(0.667,6.651) AB11(0.667,5.889) AB13(0.667,5.127) AB14(0.667,4.365) AB15(0.667,3.807) AB31(0.667,-3.807) AB32(0.667,-4.365) AB33(0.667,-5.127) AB35(0.667,-5.889) AB36(0.667,-6.651) AB38(0.667,-7.413) AB39(0.667,-8.175) AC17(0,3.099) AC18(0,2.324) AC20(0,1.549) AC21(0,0.775) AC23(0,0) AC25(0,-0.775) AC26(0,-1.549) AC28(0,-2.324) AC29(0,-3.099) AD7(-0.667,8.175) AD8(-0.667,7.413) AD10(-0.667,6.651) AD11(-0.667,5.889) AD13(-0.667,5.127) AD14(-0.667,4.365) AD15(-0.667,3.807) AD31(-0.667,-3.807) AD32(-0.667,-4.365) AD33(-0.667,-5.127) AD35(-0.667,-5.889) AD36(-0.667,-6.651) AD38(-0.667,-7.413) AD39(-0.667,-8.175) AE17(-0.775,3.099) AE18(-0.775,2.324) AE20(-0.775,1.549) AE21(-0.775,0.775) AE23(-0.775,0) AE25(-0.775,-0.775) AE26(-0.775,-1.549) AE28(-0.775,-2.324) AE29(-0.775,-3.099) AF17(-1.549,3.099) AF18(-1.549,2.324) AF20(-1.549,1.549) AF21(-1.549,0.775) AF23(-1.549,0) AF25(-1.549,-0.775) AF26(-1.549,-1.549) AF28(-1.549,-2.324) AF29(-1.549,-3.099) AG7(-1.772,8.175) AG8(-1.772,7.413) AG10(-1.772,6.651) AG11(-1.772,5.889) AG13(-1.772,5.127) AG14(-1.772,4.365) AG15(-1.772,3.807) AG31(-1.772,-3.807) AG32(-1.772,-4.365) AG33(-1.772,-5.127) AG35(-1.772,-5.889) AG36(-1.772,-6.651) AG38(-1.772,-7.413) AG39(-1.772,-8.175) AH17(-2.324,3.099) AH18(-2.324,2.324) AH20(-2.324,1.549) AH21(-2.324,0.775) AH23(-2.324,0) AH25(-2.324,-0.775) AH26(-2.324,-1.549) AH28(-2.324,-2.324) AH29(-2.324,-3.099) AJ7(-2.953,8.074) AJ8(-2.953,7.312) AJ10(-2.953,6.55) AJ11(-2.953,5.788) AJ13(-2.953,5.026) AJ14(-2.953,4.315) AJ15(-2.953,3.807) AJ17(-3.099,3.099) AJ18(-3.099,2.324) AJ20(-3.099,1.549) AJ21(-3.099,0.775) AJ23(-3.099,0) AJ25(-3.099,-0.775) AJ26(-3.099,-1.549) AJ28(-3.099,-2.324) AJ29(-3.099,-3.099) AJ31(-2.953,-3.807) AJ32(-2.953,-4.365) AJ33(-2.953,-5.127) AJ35(-2.953,-5.889) AJ36(-2.953,-6.651) AJ38(-2.953,-7.413) AJ39(-2.953,-8.175) AL7(-4.071,8.074) AL8(-4.071,7.312) AL10(-4.071,6.55) AL11(-4.071,5.788) AL13(-4.071,5.026) AL17(-3.807,2.953) AL19(-3.807,1.772) AL22(-3.807,0.667) AL24(-3.807,-0.667) AL27(-3.807,-1.772) AL29(-3.807,-2.953) AL32(-4.096,-4.34) AL33(-4.096,-5.102) AL35(-4.096,-5.864) AL36(-4.096,-6.626) AL38(-4.096,-7.388) AL39(-4.096,-8.15) AM15(-4.34,4.096) AM17(-4.365,2.953) AM19(-4.365,1.772) AM22(-4.365,0.667) AM24(-4.365,-0.667) AM27(-4.365,-1.772) AM29(-4.315,-2.953) AN7(-5.036,8.023) AN8(-4.985,7.261) AN10(-4.985,6.499) AN11(-5.026,5.753) AN15(-5.102,4.096) AN17(-5.127,2.953) AN19(-5.127,1.772) AN22(-5.127,0.667) AN24(-5.127,-0.667) AN27(-5.127,-1.772) AN29(-5.026,-2.953) AN31(-5.026,-4.071) AN36(-5.087,-6.47) AN38(-5.087,-7.232) AN39(-5.087,-7.994) AP11(-5.551,6.04) AR7(-6.037,7.999) AR9(-6.077,7.084) AR15(-5.864,4.096) AR17(-5.889,2.953) AR19(-5.889,1.772) AR22(-5.889,0.667) AR24(-5.889,-0.667) AR27(-5.889,-1.772) AR29(-5.788,-2.953) AR31(-5.788,-4.071) AR33(-5.753,-5.026) AR34(-6.04,-5.551) AR38(-6.068,-7.396) AR39(-6.068,-8.158) AT9(-6.713,6.938) AT10(-6.663,6.311) AT13(-6.47,5.087) AT15(-6.626,4.096) AT17(-6.651,2.953) AT19(-6.651,1.772) AT22(-6.651,0.667) AT24(-6.651,-0.667) AT27(-6.651,-1.772) AT29(-6.55,-2.953) AT31(-6.55,-4.071) AT33(-6.499,-4.985) AT36(-6.311,-6.663) AU7(-6.994,7.936) AU35(-7.084,-6.077) AU36(-6.938,-6.713) AU39(-7.141,-7.991) AV6(-7.645,8.237) AV11(-7.396,6.068) AV13(-7.232,5.087) AV15(-7.388,4.096) AV17(-7.413,2.953) AV19(-7.413,1.772) AV22(-7.413,0.667) AV24(-7.413,-0.667) AV27(-7.413,-1.772) AV29(-7.312,-2.953) AV31(-7.312,-4.071) AV33(-7.261,-4.985) AW9(-7.991,7.141) AW11(-8.158,6.068) AW13(-7.994,5.087) AW15(-8.15,4.096) AW17(-8.175,2.953) AW19(-8.175,1.772) AW22(-8.175,0.667) AW24(-8.175,-0.667) AW27(-8.175,-1.772) AW29(-8.074,-2.953) AW31(-8.074,-4.071) AW33(-8.023,-5.036) AW35(-7.999,-6.037) AW37(-7.936,-6.994) AY5(-8.585,8.764) AY38(-8.237,-7.645) B1(10.46,10.814) B2(10.33,10.33) B3(10.326,9.824) B43(10.304,-9.8) B44(10.33,-10.33) B45(10.46,-10.814) BA40(-8.764,-8.585) BB1(-9.459,10.814) BB45(-9.459,-10.814) BC1(-9.959,10.814) BC2(-9.824,10.326) BC44(-9.8,-10.304) BC45(-9.959,-10.814) BD1(-10.46,10.814) BD2(-10.33,10.33) BD3(-10.304,9.8) BD43(-10.326,-9.824) BD44(-10.33,-10.33) BD45(-10.46,-10.814) BE2(-10.814,10.46) BE3(-10.814,9.959) BE4(-10.814,9.459) BE42(-10.814,-9.459) BE43(-10.814,-9.959) BE44(-10.814,-10.46) C1(9.959,10.814) C2(9.8,10.304) C42(9.86,-9.288) C44(9.824,-10.326) C45(9.959,-10.814) D1(9.459,10.814) D45(9.459,-10.814) F8(8.237,7.645) G9(7.936,6.994) G11(7.999,6.037) G13(8.023,5.036) G15(8.074,4.071) G17(8.074,2.953) G19(8.175,1.772) G22(8.175,0.667) G24(8.175,-0.667) G27(8.175,-1.772) G29(8.175,-2.953) G31(8.15,-4.096) G33(7.994,-5.087) G35(8.158,-6.068) G37(7.991,-7.141) H13(7.261,4.985) H15(7.312,4.071) H17(7.312,2.953) H19(7.413,1.772) H22(7.413,0.667) H24(7.413,-0.667) H27(7.413,-1.772) H29(7.413,-2.953) H31(7.388,-4.096) H33(7.232,-5.087) H35(7.396,-6.068) J7(7.141,7.991) J10(6.938,6.713) J11(7.084,6.077) J39(6.994,-7.936) K10(6.311,6.663) K13(6.499,4.985) K15(6.55,4.071) K17(6.55,2.953) K19(6.651,1.772) K22(6.651,0.667) K24(6.651,-0.667) K27(6.651,-1.772) K29(6.651,-2.953) K31(6.626,-4.096) K33(6.47,-5.087) K36(6.663,-6.311) K37(6.713,-6.938) L7(6.068,8.158) L8(6.068,7.396) L12(6.04,5.551) L13(5.753,5.026) L15(5.788,4.071) L17(5.788,2.953) L19(5.889,1.772) L22(5.889,0.667) L24(5.889,-0.667) L27(5.889,-1.772) L29(5.889,-2.953) L31(5.864,-4.096) L37(6.077,-7.084) L39(6.037,-7.999) M35(5.551,-6.04) N7(5.087,7.994) N8(5.087,7.232) N10(5.087,6.47) N15(5.026,4.071) N17(5.026,2.953) N19(5.127,1.772) N22(5.127,0.667) N24(5.127,-0.667) N27(5.127,-1.772) N29(5.127,-2.953) N31(5.102,-4.096) N35(5.026,-5.753) N36(4.985,-6.499) N38(4.985,-7.261) N39(5.036,-8.023) P17(4.315,2.953) P19(4.365,1.772) P22(4.365,0.667) P24(4.365,-0.667) P27(4.365,-1.772) P29(4.365,-2.953) P31(4.34,-4.096) R7(4.096,8.15) R8(4.096,7.388) R10(4.096,6.626) R11(4.096,5.864) R13(4.096,5.102) R14(4.096,4.34) R17(3.807,2.953) R19(3.807,1.772) R22(3.807,0.667) R24(3.807,-0.667) R27(3.807,-1.772) R29(3.807,-2.953) R33(4.071,-5.026) R35(4.071,-5.788) R36(4.071,-6.55) R38(4.071,-7.312) R39(4.071,-8.074) U7(2.953,8.175) U8(2.953,7.413) U10(2.953,6.651) U11(2.953,5.889) U13(2.953,5.127) U14(2.953,4.365) U15(2.953,3.807) U17(3.099,3.099) U18(3.099,2.324) U20(3.099,1.549) U21(3.099,0.775) U23(3.099,0) U25(3.099,-0.775) U26(3.099,-1.549) U28(3.099,-2.324) U29(3.099,-3.099) U31(2.953,-3.807) U32(2.953,-4.315) U33(2.953,-5.026) U35(2.953,-5.788) U36(2.953,-6.55) U38(2.953,-7.312) U39(2.953,-8.074) V17(2.324,3.099) V18(2.324,2.324) V20(2.324,1.549) V21(2.324,0.775) V23(2.324,0) V25(2.324,-0.775) V26(2.324,-1.549) V28(2.324,-2.324) V29(2.324,-3.099) W7(1.772,8.175) W8(1.772,7.413) W10(1.772,6.651) W11(1.772,5.889) W13(1.772,5.127) W14(1.772,4.365) W15(1.772,3.807) W31(1.772,-3.807) W32(1.772,-4.365) W33(1.772,-5.127) W35(1.772,-5.889) W36(1.772,-6.651) W38(1.772,-7.413) W39(1.772,-8.175) Y17(1.549,3.099) Y18(1.549,2.324) Y20(1.549,1.549) Y21(1.549,0.775) Y23(1.549,0) Y25(1.549,-0.775) Y26(1.549,-1.549) Y28(1.549,-2.324) Y29(1.549,-3.099)
  round 0.279 smd: A5(10.814,8.959) A41(10.814,-8.959) BA1(-8.959,10.814) BA45(-8.959,-10.814) BE5(-10.814,8.959) BE41(-10.814,-8.959) E1(8.959,10.814) E45(8.959,-10.814)
  round 0.254 smd: A6(10.814,8.458) A25(10.814,-1.225) A40(10.814,-8.458) AB3(0.609,9.888) AB4(0.482,9.403) AB5(0.667,8.937) AB41(0.667,-8.937) AB42(0.509,-9.421) AC3(0.096,9.727) AD3(-0.484,9.929) AD4(-0.509,9.421) AD5(-0.667,8.937) AD41(-0.667,-8.937) AD42(-0.482,-9.403) AF3(-1.664,9.888) AF5(-1.721,8.885) AF41(-1.721,-8.887) AG3(-2.178,9.727) AG4(-1.791,9.403) AG42(-1.764,-9.421) AJ4(-2.783,9.421) AJ5(-2.953,8.836) AJ41(-2.953,-8.937) AJ42(-2.756,-9.403) AL3(-3.937,9.888) AL4(-4.064,9.403) AL5(-4.071,8.836) AL41(-4.096,-8.887) AL42(-4.037,-9.421) AM3(-4.451,9.727) AN3(-5.03,9.929) AN4(-5.056,9.421) AN5(-5.163,8.785) AN41(-5.087,-8.756) AN42(-5.029,-9.403) AR5(-6.182,8.886) AR41(-6.068,-8.92) AT4(-6.338,9.403) AT42(-6.311,-9.421) AU41(-7.09,-9.038) AU43(-6.915,-9.727) AV3(-7.355,9.929) AV4(-7.321,9.229) AV43(-7.391,-9.888) AW4(-8.204,9.434) AW42(-7.816,-9.24) AY1(-8.458,10.814) AY45(-8.458,-10.814) B6(10.296,8.45) B10(10.235,6.724) B25(10.306,-1.225) B40(10.355,-8.701) BA4(-9.12,9.602) BA5(-9.095,8.767) BA9(-9.038,7.09) BA11(-8.92,6.068) BA13(-8.756,5.087) BA15(-8.887,4.096) BA17(-8.937,2.953) BA20(-8.887,1.721) BA22(-8.937,0.667) BA24(-8.937,-0.667) BA26(-8.885,-1.721) BA29(-8.836,-2.953) BA31(-8.836,-4.071) BA33(-8.785,-5.163) BA35(-8.886,-6.182) BA41(-8.767,-9.095) BB3(-9.344,10.162) BB7(-9.24,7.816) BB10(-9.421,6.311) BB13(-9.403,5.029) BB15(-9.421,4.037) BB17(-9.403,2.756) BB19(-9.421,1.764) BB22(-9.403,0.482) BB24(-9.421,-0.509) BB27(-9.403,-1.791) BB29(-9.421,-2.783) BB31(-9.403,-4.064) BB33(-9.421,-5.056) BB36(-9.403,-6.338) BB38(-9.229,-7.321) BB39(-9.434,-8.204) BB41(-9.602,-9.12) BB43(-9.288,-9.86) BC4(-9.86,9.288) BC9(-9.727,6.915) BC42(-10.162,-9.344) BE6(-10.814,8.458) BE40(-10.814,-8.458) C8(9.929,7.355) C10(9.727,6.724) C11(9.888,6.211) C14(9.727,4.451) C15(9.888,3.937) C17(9.929,2.757) C19(9.727,2.178) C20(9.888,1.664) C23(9.727,-0.096) C24(9.888,-0.609) C27(9.929,-1.789) C28(9.727,-2.369) C29(9.888,-2.883) C31(9.929,-4.063) C32(9.727,-4.642) C33(9.888,-5.156) C36(9.929,-6.336) C37(9.727,-6.915) C38(9.888,-7.391) D3(9.288,9.86) D5(9.602,9.12) D7(9.434,8.204) D8(9.229,7.321) D10(9.403,6.338) D13(9.421,5.056) D15(9.403,4.064) D17(9.421,2.783) D19(9.403,1.791) D22(9.421,0.509) D24(9.403,-0.482) D27(9.421,-1.764) D29(9.403,-2.756) D31(9.421,-4.037) D33(9.403,-5.029) D36(9.421,-6.311) D39(9.24,-7.816) D43(9.344,-10.162) E5(8.767,9.095) E6(8.764,8.585) E11(8.886,6.182) E13(8.785,5.163) E15(8.836,4.071) E17(8.836,2.953) E20(8.885,1.721) E22(8.937,0.667) E24(8.937,-0.667) E26(8.887,-1.721) E29(8.937,-2.953) E31(8.887,-4.096) E33(8.756,-5.087) E35(8.92,-6.068) E37(9.038,-7.09) E41(9.095,-8.767) E42(9.12,-9.602) F1(8.458,10.814) F41(8.585,-8.764) F44(8.45,-10.296) F45(8.458,-10.814) G4(7.816,9.24) G42(8.204,-9.434) H2(7.391,10.396) H3(7.391,9.888) H40(7.645,-8.237) H42(7.321,-9.229) H43(7.355,-9.929) J2(6.915,10.235) J3(6.915,9.727) J5(7.09,9.038) K2(6.432,10.428) K3(6.336,9.929) K4(6.311,9.421) K42(6.338,-9.403) K43(6.724,-9.727) L5(6.068,8.92) L41(6.182,-8.886) L43(6.211,-9.888) N3(5.156,9.888) N4(5.029,9.403) N5(5.087,8.756) N41(5.163,-8.785) N42(5.056,-9.421) P3(4.642,9.727) R4(4.037,9.421) R5(4.096,8.887) R41(4.071,-8.836) R42(4.064,-9.403) U3(2.883,9.888) U4(2.756,9.403) U5(2.953,8.937) U41(2.953,-8.836) U42(2.783,-9.421) V3(2.369,9.727) W3(1.789,9.929) W4(1.764,9.421) W42(1.791,-9.403) Y5(1.721,8.887) Y41(1.721,-8.885)
  oval 0.254x0.203 smd: A7(10.814,7.893) A9(10.814,6.852) A37(10.814,-6.839) A39(10.814,-7.893) B7(10.306,7.944) B39(10.306,-7.944) BC8(-9.888,7.391) BD6(-10.355,8.701) BD7(-10.306,7.944) BD36(-10.235,-6.724) BD39(-10.306,-7.944) BE7(-10.814,7.893) BE9(-10.814,6.839) BE37(-10.814,-6.852) BE39(-10.814,-7.893)
  oval 0.254x0.152 smd: A12(10.814,5.595) A14(10.814,4.553) A16(10.814,3.321) A18(10.814,2.28) A21(10.814,1.048) A23(10.814,0.007) A28(10.814,-2.267) A32(10.814,-4.54) B8(10.428,7.258) B11(10.396,6.211) B13(10.428,4.934) B15(10.396,3.937) B18(10.428,2.661) B19(10.235,2.178) B20(10.396,1.664) B22(10.428,0.388) B24(10.396,-0.609) B27(10.428,-1.886) B33(10.396,-5.156) B36(10.428,-6.432) BD10(-10.428,6.432) BD13(-10.396,5.156) BD14(-10.235,4.642) BD15(-10.428,4.159) BD17(-10.396,2.883) BD18(-10.235,2.369) BD19(-10.428,1.886) BD22(-10.396,0.609) BD23(-10.235,0.096) BD24(-10.428,-0.388) BD26(-10.396,-1.664) BD27(-10.235,-2.178) BD28(-10.428,-2.661) BD31(-10.396,-3.937) BD32(-10.235,-4.451) BD33(-10.428,-4.934) BD35(-10.396,-6.211) BD38(-10.428,-7.258) BE11(-10.814,5.772) BE14(-10.814,4.54) BE16(-10.814,3.499) BE18(-10.814,2.267) BE21(-10.814,1.225) BE23(-10.814,-0.007) BE25(-10.814,-1.048) BE28(-10.814,-2.28) BE30(-10.814,-3.321) BE32(-10.814,-4.553) BE34(-10.814,-5.595)
  custom 0.051x0.051 smd: A30(10.814,-3.499) A35(10.814,-5.772) AA2(1.225,10.306) AA44(1.048,-10.306) AB43(0.484,-9.929) AD43(-0.609,-9.888) AE2(-1.048,10.306) AE44(-1.225,-10.306) AG43(-1.789,-9.929) AJ3(-2.757,9.929) AJ43(-2.883,-9.888) AK2(-3.321,10.306) AK44(-3.499,-10.306) AL43(-4.063,-9.929) AM2(-4.451,10.235) AN43(-5.156,-9.888) AP2(-5.595,10.306) AR3(-6.211,9.888) AR44(-5.772,-10.306) AT43(-6.336,-9.929) AU44(-6.915,-10.235) AV44(-7.391,-10.396) B12(10.306,5.595) B14(10.235,4.451) B16(10.306,3.321) B21(10.306,1.048) B23(10.235,-0.096) B29(10.396,-2.883) B30(10.306,-3.499) B31(10.428,-4.159) B32(10.235,-4.642) B35(10.306,-5.772) B37(10.235,-6.915) B38(10.396,-7.391) BC10(-9.929,6.336) BC13(-9.888,5.156) BC15(-9.929,4.063) BC17(-9.888,2.883) BC19(-9.929,1.789) BC22(-9.888,0.609) BC24(-9.929,-0.484) BC26(-9.888,-1.664) BC29(-9.929,-2.757) BC31(-9.888,-3.937) BC33(-9.929,-5.03) BC35(-9.888,-6.211) BC38(-9.929,-7.355) BD8(-10.396,7.391) BD9(-10.235,6.915) BD11(-10.306,5.772) BD16(-10.306,3.499) BD21(-10.306,1.225) BD25(-10.306,-1.048) BD30(-10.306,-3.321) BD34(-10.306,-5.595) C13(9.929,5.03) C22(9.929,0.484) L2(5.772,10.306) M44(5.595,-10.306) N43(5.03,-9.929) P2(4.642,10.235) R2(4.159,10.428) R3(4.063,9.929) R43(3.937,-9.888) T1(3.499,10.814) T2(3.499,10.306) T44(3.321,-10.306) U2(2.883,10.396) U43(2.757,-9.929) V2(2.369,10.235) Y43(1.664,-9.888)
  oval 0.152x0.254 smd: AA1(1.225,10.814) AA45(1.048,-10.814) AB2(0.609,10.396) AB44(0.388,-10.428) AC1(-0.007,10.814) AC2(0.096,10.235) AC44(-0.096,-10.235) AC45(0.007,-10.814) AD2(-0.388,10.428) AD44(-0.609,-10.396) AE1(-1.048,10.814) AE45(-1.225,-10.814) AF2(-1.664,10.396) AG2(-2.178,10.235) AG44(-1.886,-10.428) AH1(-2.28,10.814) AH2(-2.661,10.428) AH44(-2.369,-10.235) AH45(-2.267,-10.814) AJ44(-2.883,-10.396) AK1(-3.321,10.814) AK45(-3.499,-10.814) AL2(-3.937,10.396) AL44(-4.159,-10.428) AM1(-4.553,10.814) AM44(-4.642,-10.235) AM45(-4.54,-10.814) AN2(-4.934,10.428) AN44(-5.156,-10.396) AP1(-5.595,10.814) AR2(-6.211,10.396) AR45(-5.772,-10.814) AT44(-6.432,-10.428) AV2(-7.258,10.428) L1(5.772,10.814) L44(6.211,-10.396) M45(5.595,-10.814) N2(5.156,10.396) N44(4.934,-10.428) P1(4.54,10.814) P44(4.451,-10.235) P45(4.553,-10.814) R44(3.937,-10.396) T45(3.321,-10.814) V1(2.267,10.814) V44(2.661,-10.428) V45(2.28,-10.814) W2(1.886,10.428) W44(2.178,-10.235) Y44(1.664,-10.396)
  round 0.368 smd: AA4(1.225,9.326) AA42(1.048,-9.324) AE4(-1.048,9.324) AE42(-1.225,-9.326) AK4(-3.321,9.324) AK42(-3.499,-9.326) AP4(-5.595,9.324) AR42(-5.772,-9.326) AY2(-8.45,10.296) BB11(-9.326,5.772) BB16(-9.326,3.499) BB21(-9.326,1.225) BB25(-9.324,-1.048) BB30(-9.324,-3.321) BB34(-9.324,-5.595) BD40(-10.296,-8.45) C4(10.162,9.344) D12(9.324,5.595) D16(9.324,3.321) D21(9.324,1.048) D25(9.326,-1.225) D30(9.326,-3.499) D35(9.326,-5.772) L4(5.772,9.326) M42(5.595,-9.324) T4(3.499,9.326) T42(3.321,-9.324)
  custom 0.057x0.057 smd: AC43(-0.096,-9.727) AH43(-2.369,-9.727) AM43(-4.642,-9.727) AT3(-6.724,9.727) B28(10.235,-2.369) BC14(-9.727,4.642) BC18(-9.727,2.369) BC23(-9.727,0.096) BC27(-9.727,-2.178) BC32(-9.727,-4.451) BC36(-9.727,-6.724) P43(4.451,-9.727) W43(2.178,-9.727)
  oval 0.203x0.254 smd: AT2(-6.724,10.235) AU1(-6.852,10.814) AU45(-6.839,-10.814) AW1(-7.893,10.814) AW2(-7.944,10.306) AW44(-7.944,-10.306) AW45(-7.893,-10.814) AY44(-8.701,-10.355) F2(8.701,10.355) G1(7.893,10.814) G2(7.944,10.306) G44(7.944,-10.306) G45(7.893,-10.814) H44(7.258,-10.428) J1(6.839,10.814) J45(6.852,-10.814) K44(6.724,-10.235)
C0402
  oval 0.635x0.508 smd: 1(-0.445,0) 2(0.445,0)
C0603
  oval 0.914x0.813 smd: 1(-0.686,0) 2(0.686,0)
C0603_H35
  oval 0.914x0.813 smd: 1(-0.686,0) 2(0.686,0)
C0603_H39
  oval 0.914x0.813 smd: 1(-0.686,0) 2(0.686,0)
